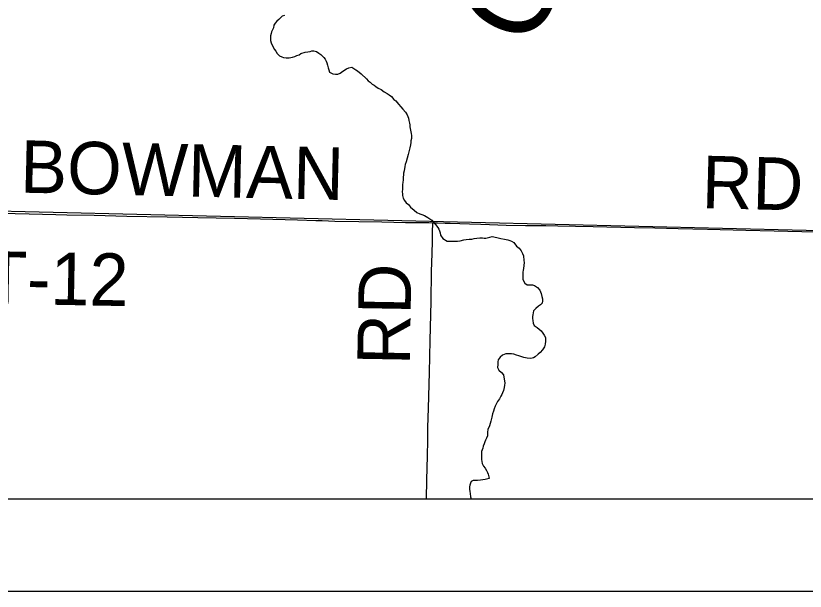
# Model space of a CAD drawing. Extents: x 0 to 34, y 0 to 22.
# Drawn here: x 3.39 to 4.244, y 14 to 14.623 of the extents above; entities that cross this region are included whole.
import ezdxf

# ---------------------------------------------------------------- set-up
doc = ezdxf.new("R2010")
doc.units = 0
for name, color, linetype in [('GM_X_Minor_River', 7, 'Continuous'), ('GM_X_Minor_River_Text', 7, 'Continuous'), ('GM_X_Section', 7, 'Continuous'), ('GM_X_Township_Road', 7, 'Continuous'), ('GM_X_Township_Road_Text', 7, 'Continuous'), ('SH_Data', 7, 'Continuous')]:
    doc.layers.add(name, color=color, linetype=linetype)

msp = doc.modelspace()

# ---------------------------------------------------------------- linework, layer by layer
at = {"layer": 'GM_X_Minor_River'}
for points in [[(3.68049, 14.6237), (3.67818, 14.62302), (3.67622, 14.62118), (3.67426, 14.61934), (3.67229, 14.61751), (3.67032, 14.61529), (3.6691, 14.61305), (3.66864, 14.6104), (3.66743, 14.60816), (3.66659, 14.6059), (3.66615, 14.60401), (3.66532, 14.60176), (3.66526, 14.59986), (3.66553, 14.59642), (3.66622, 14.59412), (3.66763, 14.59065), (3.66979, 14.58677), (3.67125, 14.58482), (3.6727, 14.58249), (3.67529, 14.58012), (3.67754, 14.57891), (3.67941, 14.57808), (3.68245, 14.5776), (3.6855, 14.57788), (3.68742, 14.5782), (3.68933, 14.57852), (3.69164, 14.5792), (3.69396, 14.58027), (3.69626, 14.58095), (3.69821, 14.58241), (3.70283, 14.58378), (3.70589, 14.58444), (3.70819, 14.58474), (3.71012, 14.58544), (3.7124, 14.58536), (3.71504, 14.58452), (3.71765, 14.58291), (3.71989, 14.58131), (3.72321, 14.57816), (3.72468, 14.57621), (3.72576, 14.57427), (3.72646, 14.57234), (3.72713, 14.56966), (3.72781, 14.56697), (3.7285, 14.56467), (3.72918, 14.56236), (3.73293, 14.56033), (3.73559, 14.56025), (3.73825, 14.56016), (3.74096, 14.56121), (3.74369, 14.5634), (3.74758, 14.56594), (3.75028, 14.56699), (3.75335, 14.56765), (3.75783, 14.56484), (3.75969, 14.56363), (3.7634, 14.56047), (3.76932, 14.55495), (3.77116, 14.55298), (3.77339, 14.55139), (3.77561, 14.54941), (3.77748, 14.54821), (3.77933, 14.54663), (3.78195, 14.54502), (3.78532, 14.54338), (3.78829, 14.541), (3.79166, 14.53899), (3.7939, 14.53777), (3.79651, 14.53579), (3.79907, 14.53266), (3.80093, 14.53107), (3.80386, 14.52755), (3.80644, 14.52481), (3.80864, 14.52207), (3.81158, 14.51893), (3.8134, 14.5162), (3.8141, 14.51428), (3.8148, 14.51235), (3.81511, 14.51006), (3.81577, 14.50699), (3.81609, 14.50508), (3.81641, 14.50317), (3.81673, 14.50126), (3.81705, 14.49934), (3.8177, 14.4959), (3.81801, 14.49361), (3.81791, 14.49056), (3.81745, 14.48792), (3.81739, 14.48602), (3.81692, 14.48337), (3.81607, 14.48035), (3.81559, 14.47733), (3.81431, 14.47318), (3.81216, 14.46526), (3.8113, 14.46225), (3.81084, 14.45998), (3.80994, 14.45545), (3.80947, 14.4528)], [(3.80947, 14.4528), (3.80941, 14.4509), (3.80896, 14.44863), (3.80885, 14.44521), (3.80877, 14.44293), (3.80831, 14.44028), (3.80821, 14.43724), (3.80815, 14.43534), (3.80807, 14.43268), (3.80838, 14.43039), (3.80832, 14.42849), (3.80899, 14.4258), (3.81043, 14.42309), (3.81226, 14.42075), (3.81486, 14.41876), (3.81706, 14.41602), (3.82076, 14.41286), (3.82372, 14.4101), (3.82711, 14.40884), (3.82937, 14.40801), (3.83201, 14.40716), (3.83574, 14.40475), (3.83798, 14.40354), (3.84022, 14.40194), (3.84168, 14.39999), (3.84388, 14.39726), (3.84644, 14.39413), (3.84753, 14.39219), (3.84822, 14.39026), (3.84893, 14.38834), (3.8496, 14.38565), (3.85215, 14.38214), (3.85664, 14.37933), (3.8631, 14.37912), (3.86768, 14.37935), (3.87074, 14.37963), (3.87458, 14.38064), (3.87725, 14.38094), (3.88031, 14.38121), (3.88336, 14.38149), (3.88605, 14.38216), (3.88873, 14.38246), (3.89216, 14.38273), (3.89482, 14.38264), (3.89673, 14.38257), (3.89863, 14.38251), (3.90285, 14.38351), (3.90554, 14.38418), (3.91046, 14.38326), (3.91461, 14.38198), (3.91878, 14.38146), (3.92218, 14.38059), (3.92444, 14.37976), (3.92633, 14.37931), (3.92894, 14.3777), (3.93187, 14.3738), (3.93446, 14.37143), (3.93665, 14.3687), (3.93809, 14.36599), (3.93915, 14.36329), (3.93975, 14.35832), (3.94006, 14.35603), (3.93947, 14.34958), (3.93903, 14.3477), (3.93858, 14.34543), (3.9385, 14.34315), (3.93843, 14.34087), (3.93873, 14.3382), (3.93943, 14.33627), (3.94086, 14.33356), (3.9431, 14.33196), (3.94614, 14.33186), (3.94918, 14.33176), (3.95107, 14.33132), (3.95443, 14.32892), (3.957, 14.32618), (3.9584, 14.32232), (3.95907, 14.31926), (3.95974, 14.31657), (3.96006, 14.31466), (3.9596, 14.31201), (3.95763, 14.31018), (3.95568, 14.30872), (3.95256, 14.30616), (3.95019, 14.30357), (3.94929, 14.29942), (3.94923, 14.29752), (3.94916, 14.29524), (3.94948, 14.29332), (3.94976, 14.29027), (3.95083, 14.28795), (3.95418, 14.28556), (3.95826, 14.282), (3.96009, 14.27966), (3.96154, 14.27733), (3.96299, 14.275), (3.96323, 14.2708), (3.96275, 14.26778), (3.9619, 14.26476), (3.95989, 14.2614), (3.95751, 14.25844)], [(3.95751, 14.25844), (3.95516, 14.25661), (3.95203, 14.25405), (3.95009, 14.25298), (3.94739, 14.25192), (3.94322, 14.25244), (3.93982, 14.25331), (3.93642, 14.25419), (3.93416, 14.25503), (3.93191, 14.25586), (3.92889, 14.25672), (3.92624, 14.25719), (3.92433, 14.25725), (3.92243, 14.25731), (3.92014, 14.25701), (3.91666, 14.2556), (3.91393, 14.25341), (3.91194, 14.25081), (3.91149, 14.24855), (3.91139, 14.24551), (3.91129, 14.24247), (3.91272, 14.23937), (3.91531, 14.23701), (3.91751, 14.23427), (3.91913, 14.22547), (3.91868, 14.2232), (3.91821, 14.22055), (3.91773, 14.21752), (3.91651, 14.2149), (3.91568, 14.21302), (3.91486, 14.21115), (3.91326, 14.20854), (3.91126, 14.20556), (3.91004, 14.20332), (3.9088, 14.20032), (3.90758, 14.1977), (3.90673, 14.19506), (3.90587, 14.19205), (3.905, 14.18865), (3.9041, 14.18411), (3.90242, 14.17922), (3.90076, 14.17509), (3.9003, 14.17245), (3.90024, 14.17055), (3.90016, 14.16827), (3.89932, 14.16563), (3.89811, 14.16377), (3.89729, 14.16189), (3.89684, 14.15963), (3.89561, 14.157), (3.89517, 14.15511), (3.89391, 14.15135), (3.89385, 14.14945), (3.89378, 14.14717), (3.89401, 14.1426), (3.89433, 14.14069), (3.89464, 14.13839), (3.89606, 14.1353), (3.89791, 14.13334), (3.89934, 14.13063), (3.90042, 14.12869), (3.90112, 14.12676), (3.9018, 14.12408), (3.90212, 14.12216), (3.8979, 14.12116), (3.89291, 14.12019), (3.88948, 14.11992), (3.88681, 14.12001), (3.88491, 14.12007), (3.88259, 14.11901), (3.88177, 14.11713), (3.88132, 14.11486), (3.88088, 14.11298), (3.88081, 14.1107), (3.8811, 14.10802), (3.88141, 14.10573), (3.88206, 14.10228), (3.88263, 14.1)]]:
    msp.add_lwpolyline(points, dxfattribs=at)
at = {"layer": 'GM_X_Section'}
msp.add_lwpolyline([(4.35758, 15.39266), (4.33594, 14.38845), (3.33901, 14.41257), (3.35868, 15.41381)], close=True, dxfattribs=at)
at = {"layer": 'GM_X_Township_Road'}
for points in [[(2.1, 18.40743), (2.1, 14.1), (7.35068, 14.1), (7.35419, 14.31073), (7.37669, 15.31551), (7.38543, 16.36959)], [(3.33623, 14.41064), (3.35799, 14.41004), (3.40424, 14.40877), (3.43284, 14.40808), (3.44484, 14.40782), (3.47446, 14.40717), (3.50976, 14.40641), (3.55358, 14.40562), (3.58663, 14.40493), (3.62655, 14.40409), (3.65456, 14.40329), (3.69464, 14.40214), (3.71444, 14.40169), (3.72127, 14.40146), (3.73494, 14.40103), (3.76104, 14.40038), (3.78592, 14.40011), (3.79896, 14.39987), (3.81138, 14.39958), (3.81512, 14.3995), (3.83, 14.39932), (3.83681, 14.39924), (3.84119, 14.39915)], [(3.83426, 14.1), (3.83476, 14.12071), (3.83524, 14.14618), (3.83558, 14.16358), (3.83583, 14.17725), (3.83647, 14.19837), (3.83741, 14.2369), (3.83815, 14.27169), (3.83921, 14.31394), (3.83988, 14.34625), (3.84018, 14.35618), (3.84041, 14.36588), (3.84073, 14.37936), (3.84094, 14.38843), (3.84119, 14.39915)], [(3.84119, 14.39915), (3.84609, 14.39904), (3.85464, 14.39875), (3.85752, 14.39862), (3.85981, 14.39861), (3.88075, 14.398), (3.89317, 14.39756), (3.90248, 14.39728), (3.9205, 14.39669), (3.94161, 14.3962), (3.94844, 14.3961), (3.95154, 14.39609), (3.95463, 14.39612), (3.96333, 14.396), (3.97637, 14.3959), (4.01489, 14.39517), (4.05964, 14.39403), (4.08139, 14.39358), (4.10687, 14.39295), (4.13866, 14.39216), (4.18018, 14.39113), (4.21064, 14.39052), (4.25538, 14.38934)]]:
    msp.add_lwpolyline(points, dxfattribs=at)
at = {"layer": 'SH_Data'}
for p, q in [((2.1, 14.1), (8.9, 14.1)), ((2, 14), (9, 14))]:
    msp.add_line(p, q, dxfattribs=at)

# ---------------------------------------------------------------- texts
at = {"layer": 'GM_X_Minor_River_Text'}
msp.add_text('Creek', height=0.094752, rotation=61.17501, dxfattribs=at).set_placement((3.9433, 14.58457))
at = {"layer": 'GM_X_Township_Road_Text'}
for s, rotation, p in [('BOWMAN', 358.67971, (3.39394, 14.43178)), ('RD', 358.53108, (4.13186, 14.41508)), ('T-12', 358.94286, (3.35498, 14.31168)), ('RD', 89.01842, (3.81613, 14.24462))]:
    msp.add_text(s, height=0.056818, rotation=rotation, dxfattribs=at).set_placement(p)

doc.saveas('drawing.dxf')
